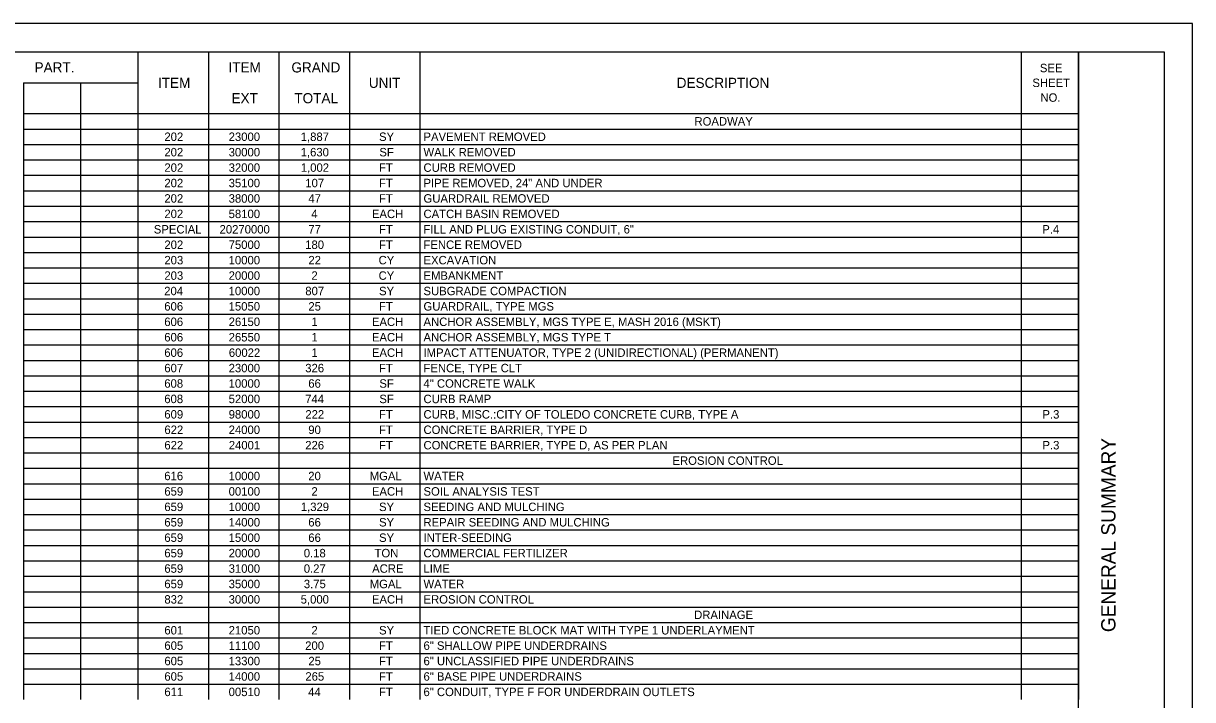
# Model space of a CAD drawing. Extents: x 0 to 34, y 0 to 22.
# Drawn here: x 13.53 to 34, y 10.16 to 22 of the extents above; entities that cross this region are included whole.
import ezdxf

# ---------------------------------------------------------------- set-up
doc = ezdxf.new("R2010")
doc.units = 0
for name, color, linetype in [('Default', 7, 'Continuous'), ('SH_Border', 7, 'Continuous'), ('SH_Cut_Line', 7, 'Continuous'), ('SH_Data', 7, 'Continuous')]:
    doc.layers.add(name, color=color, linetype=linetype)

msp = doc.modelspace()

# ---------------------------------------------------------------- linework, layer by layer
at = {"layer": 'Default'}
for p, q in [((13.53, 21.5), (15.535, 21.5)), ((15.535, 21.5), (32, 21.5)), ((15.535, 21.5), (15.535, 21.23)), ((16.769, 21.5), (16.769, 21.23)), ((18.003, 21.5), (18.003, 21.23)), ((19.237, 21.5), (19.237, 21.23)), ((20.471, 21.5), (20.471, 21.23)), ((30.997, 21.5), (30.997, 21.23)), ((32, 21.5), (32, 21.23)), ((15.535, 21.23), (15.535, 20.96)), ((16.769, 21.23), (16.769, 20.96)), ((18.003, 21.23), (18.003, 20.96)), ((19.237, 21.23), (19.237, 20.96)), ((20.471, 21.23), (20.471, 20.96)), ((30.997, 21.23), (30.997, 20.96)), ((32, 21.23), (32, 20.96)), ((13.53, 20.96), (15.535, 20.96)), ((13.53, 20.96), (13.53, 20.69)), ((14.533, 20.96), (14.533, 20.69)), ((15.535, 20.96), (15.535, 20.69)), ((16.769, 20.96), (16.769, 20.69)), ((18.003, 20.96), (18.003, 20.69)), ((19.237, 20.96), (19.237, 20.69)), ((20.471, 20.96), (20.471, 20.69)), ((30.997, 20.96), (30.997, 20.69)), ((32, 20.96), (32, 20.69)), ((13.53, 20.69), (13.53, 20.42)), ((14.533, 20.69), (14.533, 20.42)), ((15.535, 20.69), (15.535, 20.42)), ((16.769, 20.69), (16.769, 20.42)), ((18.003, 20.69), (18.003, 20.42)), ((19.237, 20.69), (19.237, 20.42)), ((20.471, 20.69), (20.471, 20.42)), ((30.997, 20.69), (30.997, 20.42)), ((32, 20.69), (32, 20.42)), ((13.53, 20.42), (15.535, 20.42)), ((13.53, 20.42), (13.53, 20.15)), ((14.533, 20.42), (14.533, 20.15)), ((15.535, 20.42), (32, 20.42)), ((15.535, 20.42), (15.535, 20.15)), ((16.769, 20.42), (16.769, 20.15)), ((18.003, 20.42), (18.003, 20.15)), ((19.237, 20.42), (19.237, 20.15)), ((20.471, 20.42), (20.471, 20.15)), ((30.997, 20.42), (30.997, 20.15)), ((32, 20.42), (32, 20.15)), ((13.53, 20.15), (15.535, 20.15)), ((13.53, 20.15), (13.53, 18.801)), ((14.533, 20.15), (14.533, 18.801)), ((15.535, 20.15), (32, 20.15)), ((15.535, 20.15), (15.535, 18.801)), ((16.769, 20.15), (16.769, 18.801)), ((18.003, 20.15), (18.003, 18.801)), ((19.237, 20.15), (19.237, 18.801)), ((20.471, 20.15), (20.471, 18.801)), ((30.997, 20.15), (30.997, 18.801)), ((32, 20.15), (32, 18.801)), ((13.53, 19.881), (15.535, 19.881)), ((15.535, 19.881), (32, 19.881)), ((13.53, 19.611), (15.535, 19.611)), ((15.535, 19.611), (32, 19.611)), ((13.53, 19.341), (15.535, 19.341)), ((15.535, 19.341), (32, 19.341)), ((13.53, 19.071), (15.535, 19.071)), ((15.535, 19.071), (32, 19.071)), ((13.53, 18.801), (15.535, 18.801)), ((13.53, 18.801), (13.53, 18.261)), ((14.533, 18.801), (14.533, 18.261)), ((15.535, 18.801), (32, 18.801)), ((15.535, 18.801), (15.535, 18.261)), ((16.769, 18.801), (16.769, 18.261)), ((18.003, 18.801), (18.003, 18.261)), ((19.237, 18.801), (19.237, 18.261)), ((20.471, 18.801), (20.471, 18.261)), ((30.997, 18.801), (30.997, 18.261)), ((32, 18.801), (32, 18.261)), ((13.53, 18.531), (15.535, 18.531)), ((15.535, 18.531), (32, 18.531)), ((13.53, 18.261), (15.535, 18.261)), ((13.53, 18.261), (13.53, 17.991)), ((14.533, 18.261), (14.533, 17.991)), ((15.535, 18.261), (32, 18.261)), ((15.535, 18.261), (15.535, 17.991)), ((16.769, 18.261), (16.769, 17.991)), ((18.003, 18.261), (18.003, 17.991)), ((19.237, 18.261), (19.237, 17.991)), ((20.471, 18.261), (20.471, 17.991)), ((30.997, 18.261), (30.997, 17.991)), ((32, 18.261), (32, 17.991)), ((13.53, 17.991), (15.535, 17.991)), ((13.53, 17.991), (13.53, 17.721)), ((14.533, 17.991), (14.533, 17.721)), ((15.535, 17.991), (32, 17.991)), ((15.535, 17.991), (15.535, 17.721)), ((16.769, 17.991), (16.769, 17.721)), ((18.003, 17.991), (18.003, 17.721)), ((19.237, 17.991), (19.237, 17.721)), ((20.471, 17.991), (20.471, 17.721)), ((30.997, 17.991), (30.997, 17.721)), ((32, 17.991), (32, 17.721)), ((13.53, 17.721), (15.535, 17.721)), ((13.53, 17.721), (13.53, 17.451)), ((14.533, 17.721), (14.533, 17.451)), ((15.535, 17.721), (32, 17.721)), ((15.535, 17.721), (15.535, 17.451)), ((16.769, 17.721), (16.769, 17.451)), ((18.003, 17.721), (18.003, 17.451)), ((19.237, 17.721), (19.237, 17.451)), ((20.471, 17.721), (20.471, 17.451)), ((30.997, 17.721), (30.997, 17.451)), ((32, 17.721), (32, 17.451)), ((13.53, 17.451), (15.535, 17.451)), ((13.53, 17.451), (13.53, 17.181)), ((14.533, 17.451), (14.533, 17.181)), ((15.535, 17.451), (32, 17.451)), ((15.535, 17.451), (15.535, 17.181)), ((16.769, 17.451), (16.769, 17.181)), ((18.003, 17.451), (18.003, 17.181)), ((19.237, 17.451), (19.237, 17.181)), ((20.471, 17.451), (20.471, 17.181)), ((30.997, 17.451), (30.997, 17.181)), ((32, 17.451), (32, 17.181)), ((13.53, 17.181), (15.535, 17.181)), ((13.53, 17.181), (13.53, 16.912)), ((14.533, 17.181), (14.533, 16.912)), ((15.535, 17.181), (32, 17.181)), ((15.535, 17.181), (15.535, 16.912)), ((16.769, 17.181), (16.769, 16.912)), ((18.003, 17.181), (18.003, 16.912)), ((19.237, 17.181), (19.237, 16.912)), ((20.471, 17.181), (20.471, 16.912)), ((30.997, 17.181), (30.997, 16.912)), ((32, 17.181), (32, 16.912)), ((13.53, 16.912), (15.535, 16.912)), ((13.53, 16.912), (13.53, 16.372)), ((14.533, 16.912), (14.533, 16.372)), ((15.535, 16.912), (32, 16.912)), ((15.535, 16.912), (15.535, 16.372)), ((16.769, 16.912), (16.769, 16.372)), ((18.003, 16.912), (18.003, 16.372)), ((19.237, 16.912), (19.237, 16.372)), ((20.471, 16.912), (20.471, 16.372)), ((30.997, 16.912), (30.997, 16.372)), ((32, 16.912), (32, 16.372)), ((13.53, 16.642), (15.535, 16.642)), ((15.535, 16.642), (32, 16.642)), ((13.53, 16.372), (15.535, 16.372)), ((13.53, 16.372), (13.53, 16.102)), ((14.533, 16.372), (14.533, 16.102)), ((15.535, 16.372), (32, 16.372)), ((15.535, 16.372), (15.535, 16.102)), ((16.769, 16.372), (16.769, 16.102)), ((18.003, 16.372), (18.003, 16.102)), ((19.237, 16.372), (19.237, 16.102)), ((20.471, 16.372), (20.471, 16.102)), ((30.997, 16.372), (30.997, 16.102)), ((32, 16.372), (32, 16.102)), ((13.53, 16.102), (15.535, 16.102)), ((13.53, 16.102), (13.53, 15.832)), ((14.533, 16.102), (14.533, 15.832)), ((15.535, 16.102), (32, 16.102)), ((15.535, 16.102), (15.535, 15.832)), ((16.769, 16.102), (16.769, 15.832)), ((18.003, 16.102), (18.003, 15.832)), ((19.237, 16.102), (19.237, 15.832)), ((20.471, 16.102), (20.471, 15.832)), ((30.997, 16.102), (30.997, 15.832)), ((32, 16.102), (32, 15.832)), ((13.53, 15.832), (15.535, 15.832)), ((13.53, 15.832), (13.53, 15.562)), ((14.533, 15.832), (14.533, 15.562)), ((15.535, 15.832), (32, 15.832)), ((15.535, 15.832), (15.535, 15.562)), ((16.769, 15.832), (16.769, 15.562)), ((18.003, 15.832), (18.003, 15.562)), ((19.237, 15.832), (19.237, 15.562)), ((20.471, 15.832), (20.471, 15.562)), ((30.997, 15.832), (30.997, 15.562)), ((32, 15.832), (32, 15.562)), ((13.53, 15.562), (15.535, 15.562)), ((13.53, 15.562), (13.53, 15.022)), ((14.533, 15.562), (14.533, 15.022)), ((15.535, 15.562), (32, 15.562)), ((15.535, 15.562), (15.535, 15.022)), ((16.769, 15.562), (16.769, 15.022)), ((18.003, 15.562), (18.003, 15.022)), ((19.237, 15.562), (19.237, 15.022)), ((20.471, 15.562), (20.471, 15.022)), ((30.997, 15.562), (30.997, 15.022)), ((32, 15.562), (32, 15.022)), ((13.53, 15.292), (15.535, 15.292)), ((15.535, 15.292), (32, 15.292)), ((13.53, 15.022), (15.535, 15.022)), ((13.53, 15.022), (13.53, 14.752)), ((14.533, 15.022), (14.533, 14.752)), ((15.535, 15.022), (32, 15.022)), ((15.535, 15.022), (15.535, 14.752)), ((16.769, 15.022), (16.769, 14.752)), ((18.003, 15.022), (18.003, 14.752)), ((19.237, 15.022), (19.237, 14.752)), ((20.471, 15.022), (20.471, 14.752)), ((30.997, 15.022), (30.997, 14.752)), ((32, 15.022), (32, 14.752)), ((13.53, 14.752), (15.535, 14.752)), ((13.53, 14.752), (13.53, 14.482)), ((14.533, 14.752), (14.533, 14.482)), ((15.535, 14.752), (32, 14.752)), ((15.535, 14.752), (15.535, 14.482)), ((16.769, 14.752), (16.769, 14.482)), ((18.003, 14.752), (18.003, 14.482)), ((19.237, 14.752), (19.237, 14.482)), ((20.471, 14.752), (20.471, 14.482)), ((30.997, 14.752), (30.997, 14.482)), ((32, 14.752), (32, 14.482)), ((13.53, 14.482), (15.535, 14.482)), ((13.53, 14.482), (13.53, 14.212)), ((14.533, 14.482), (14.533, 14.212)), ((15.535, 14.482), (32, 14.482)), ((15.535, 14.482), (15.535, 14.212)), ((16.769, 14.482), (16.769, 14.212)), ((18.003, 14.482), (18.003, 14.212)), ((19.237, 14.482), (19.237, 14.212)), ((20.471, 14.482), (20.471, 14.212)), ((30.997, 14.482), (30.997, 14.212)), ((32, 14.482), (32, 14.212)), ((13.53, 14.212), (15.535, 14.212)), ((13.53, 14.212), (13.53, 12.053)), ((14.533, 14.212), (14.533, 12.053)), ((15.535, 14.212), (32, 14.212)), ((15.535, 14.212), (15.535, 12.053)), ((16.769, 14.212), (16.769, 12.053)), ((18.003, 14.212), (18.003, 12.053)), ((19.237, 14.212), (19.237, 12.053)), ((20.471, 14.212), (20.471, 12.053)), ((30.997, 14.212), (30.997, 12.053)), ((32, 14.212), (32, 12.053)), ((13.53, 13.942), (15.535, 13.942)), ((15.535, 13.942), (32, 13.942)), ((13.53, 13.673), (15.535, 13.673)), ((15.535, 13.673), (32, 13.673)), ((13.53, 13.403), (15.535, 13.403)), ((15.535, 13.403), (32, 13.403)), ((13.53, 13.133), (15.535, 13.133)), ((15.535, 13.133), (32, 13.133)), ((13.53, 12.863), (15.535, 12.863)), ((15.535, 12.863), (32, 12.863)), ((13.53, 12.593), (15.535, 12.593)), ((15.535, 12.593), (32, 12.593)), ((13.53, 12.323), (15.535, 12.323)), ((15.535, 12.323), (32, 12.323)), ((13.53, 12.053), (15.535, 12.053)), ((13.53, 12.053), (13.53, 11.783)), ((14.533, 12.053), (14.533, 11.783)), ((15.535, 12.053), (32, 12.053)), ((15.535, 12.053), (15.535, 11.783)), ((16.769, 12.053), (16.769, 11.783)), ((18.003, 12.053), (18.003, 11.783)), ((19.237, 12.053), (19.237, 11.783)), ((20.471, 12.053), (20.471, 11.783)), ((30.997, 12.053), (30.997, 11.783)), ((32, 12.053), (32, 11.783)), ((13.53, 11.783), (15.535, 11.783)), ((13.53, 11.783), (13.53, 10.704)), ((14.533, 11.783), (14.533, 10.704)), ((15.535, 11.783), (32, 11.783)), ((15.535, 11.783), (15.535, 10.704)), ((16.769, 11.783), (16.769, 10.704)), ((18.003, 11.783), (18.003, 10.704)), ((19.237, 11.783), (19.237, 10.704)), ((20.471, 11.783), (20.471, 10.704)), ((30.997, 11.783), (30.997, 10.704)), ((32, 11.783), (32, 10.704)), ((13.53, 11.513), (15.535, 11.513)), ((15.535, 11.513), (32, 11.513)), ((13.53, 11.243), (15.535, 11.243)), ((15.535, 11.243), (32, 11.243)), ((13.53, 10.973), (15.535, 10.973)), ((15.535, 10.973), (32, 10.973)), ((13.53, 10.704), (15.535, 10.704)), ((13.53, 10.704), (13.53, 10.434)), ((14.533, 10.704), (14.533, 10.434)), ((15.535, 10.704), (32, 10.704)), ((15.535, 10.704), (15.535, 10.434)), ((16.769, 10.704), (16.769, 10.434)), ((18.003, 10.704), (18.003, 10.434)), ((19.237, 10.704), (19.237, 10.434)), ((20.471, 10.704), (20.471, 10.434)), ((30.997, 10.704), (30.997, 10.434)), ((32, 10.704), (32, 10.434)), ((13.53, 10.434), (15.535, 10.434)), ((13.53, 10.434), (13.53, 10.164)), ((14.533, 10.434), (14.533, 10.164)), ((15.535, 10.434), (32, 10.434)), ((15.535, 10.434), (15.535, 10.164)), ((16.769, 10.434), (16.769, 10.164)), ((18.003, 10.434), (18.003, 10.164)), ((19.237, 10.434), (19.237, 10.164)), ((20.471, 10.434), (20.471, 10.164)), ((30.997, 10.434), (30.997, 10.164)), ((32, 10.434), (32, 10.164))]:
    msp.add_line(p, q, dxfattribs=at)
at = {"layer": 'SH_Border'}
msp.add_line((32, 0.5), (32, 21.5), dxfattribs=at)
msp.add_lwpolyline([(1.5, 21.5), (33.5, 21.5), (33.5, 0.5), (1.5, 0.5)], close=True, dxfattribs=at)
at = {"layer": 'SH_Cut_Line'}
msp.add_lwpolyline([(0, 0), (34, 0), (34, 22), (0, 22)], close=True, dxfattribs=at)

# ---------------------------------------------------------------- texts
at = {"layer": 'Default'}
for s, height, p in [('PART.', 0.1774, (13.726, 21.141)), ('ITEM', 0.1774, (17.121, 21.141)), ('GRAND', 0.1774, (18.223, 21.141)), ('SEE ', 0.1478, (31.326, 21.145)), ('ITEM', 0.1774, (15.887, 20.871)), ('UNIT', 0.1774, (19.578, 20.871)), ('DESCRIPTION', 0.17737, (24.968, 20.871)), ('SHEET ', 0.1478, (31.195, 20.886)), ('EXT', 0.1774, (17.174, 20.602)), ('TOTAL', 0.1774, (18.274, 20.602)), ('NO.', 0.1478, (31.336, 20.628)), ('ROADWAY', 0.1478, (25.279, 20.211)), ('202', 0.1478, (15.999, 19.942)), ('23000', 0.1478, (17.124, 19.942)), ('1,887', 0.1478, (18.386, 19.942)), ('SY', 0.1478, (19.757, 19.942)), ('PAVEMENT REMOVED', 0.14781, (20.535, 19.942)), ('202', 0.1478, (15.999, 19.672)), ('30000', 0.1478, (17.124, 19.672)), ('1,630', 0.1478, (18.385, 19.672)), ('SF', 0.1478, (19.762, 19.672)), ('WALK REMOVED', 0.14781, (20.535, 19.672)), ('202', 0.1478, (15.999, 19.402)), ('32000', 0.1478, (17.124, 19.402)), ('1,002', 0.1478, (18.387, 19.402)), ('FT', 0.1478, (19.756, 19.402)), ('CURB REMOVED', 0.14781, (20.535, 19.402)), ('202', 0.1478, (15.999, 19.132)), ('35100', 0.1478, (17.124, 19.132)), ('107', 0.1478, (18.466, 19.132)), ('FT', 0.1478, (19.756, 19.132)), ('PIPE REMOVED, 24" AND UNDER', 0.14781, (20.535, 19.132)), ('202', 0.1478, (15.999, 18.862)), ('38000', 0.1478, (17.124, 18.862)), ('47', 0.1478, (18.519, 18.862)), ('FT', 0.1478, (19.756, 18.862)), ('GUARDRAIL REMOVED', 0.14781, (20.535, 18.862)), ('202', 0.1478, (15.999, 18.592)), ('58100', 0.1478, (17.124, 18.592)), ('4', 0.148, (18.57, 18.592)), ('EACH', 0.1478, (19.632, 18.592)), ('CATCH BASIN REMOVED', 0.14781, (20.535, 18.592)), ('SPECIAL', 0.1478, (15.814, 18.322)), ('20270000', 0.1478, (16.965, 18.322)), ('77', 0.1478, (18.519, 18.322)), ('FT', 0.1478, (19.756, 18.322)), ('FILL AND PLUG EXISTING CONDUIT, 6"', 0.14781, (20.535, 18.322)), ('P.4', 0.1478, (31.368, 18.322)), ('202', 0.1478, (15.999, 18.052)), ('75000', 0.1478, (17.124, 18.052)), ('180', 0.1478, (18.464, 18.052)), ('FT', 0.1478, (19.756, 18.052)), ('FENCE REMOVED', 0.14781, (20.535, 18.052)), ('203', 0.1478, (15.999, 17.782)), ('10000', 0.1478, (17.124, 17.782)), ('22', 0.1478, (18.52, 17.782)), ('CY', 0.1478, (19.749, 17.782)), ('EXCAVATION', 0.1478, (20.535, 17.782)), ('203', 0.1478, (15.999, 17.512)), ('20000', 0.1478, (17.124, 17.512)), ('2', 0.148, (18.573, 17.512)), ('CY', 0.1478, (19.749, 17.512)), ('EMBANKMENT', 0.1478, (20.535, 17.512)), ('204', 0.1478, (15.996, 17.242)), ('10000', 0.1478, (17.124, 17.242)), ('807', 0.1478, (18.466, 17.242)), ('SY', 0.1478, (19.757, 17.242)), ('SUBGRADE COMPACTION', 0.14781, (20.535, 17.242)), ('606', 0.1478, (15.997, 16.973)), ('15050', 0.1478, (17.124, 16.973)), ('25', 0.1478, (18.52, 16.973)), ('FT', 0.1478, (19.756, 16.973)), ('GUARDRAIL, TYPE MGS', 0.14781, (20.535, 16.973)), ('606', 0.1478, (15.997, 16.703)), ('26150', 0.1478, (17.124, 16.703)), ('1', 0.148, (18.573, 16.703)), ('EACH', 0.1478, (19.632, 16.703)), ('ANCHOR ASSEMBLY, MGS TYPE E, MASH 2016 (MSKT)', 0.14781, (20.535, 16.703)), ('606', 0.1478, (15.997, 16.433)), ('26550', 0.1478, (17.124, 16.433)), ('1', 0.148, (18.573, 16.433)), ('EACH', 0.1478, (19.632, 16.433)), ('ANCHOR ASSEMBLY, MGS TYPE T', 0.14781, (20.535, 16.433)), ('606', 0.1478, (15.997, 16.163)), ('60022', 0.1478, (17.127, 16.163)), ('1', 0.148, (18.573, 16.163)), ('EACH', 0.1478, (19.632, 16.163)), ('IMPACT ATTENUATOR, TYPE 2 (UNIDIRECTIONAL) (PERMANENT)', 0.14781, (20.535, 16.163)), ('607', 0.1478, (15.998, 15.893)), ('23000', 0.1478, (17.124, 15.893)), ('326', 0.1478, (18.465, 15.893)), ('FT', 0.1478, (19.756, 15.893)), ('FENCE, TYPE CLT', 0.14781, (20.535, 15.893)), ('608', 0.1478, (15.997, 15.623)), ('10000', 0.1478, (17.124, 15.623)), ('66', 0.1478, (18.518, 15.623)), ('SF', 0.1478, (19.762, 15.623)), ('4" CONCRETE WALK', 0.14781, (20.535, 15.623)), ('608', 0.1478, (15.997, 15.353)), ('52000', 0.1478, (17.124, 15.353)), ('744', 0.1478, (18.464, 15.353)), ('SF', 0.1478, (19.762, 15.353)), ('CURB RAMP', 0.1478, (20.535, 15.353)), ('609', 0.1478, (15.998, 15.083)), ('98000', 0.1478, (17.124, 15.083)), ('222', 0.1478, (18.467, 15.083)), ('FT', 0.1478, (19.756, 15.083)), ('CURB, MISC.:CITY OF TOLEDO CONCRETE CURB, TYPE A', 0.14781, (20.535, 15.083)), ('P.3', 0.1478, (31.371, 15.083)), ('622', 0.1478, (15.999, 14.813)), ('24000', 0.1478, (17.124, 14.813)), ('90', 0.1478, (18.518, 14.813)), ('FT', 0.1478, (19.756, 14.813)), ('CONCRETE BARRIER, TYPE D', 0.14781, (20.535, 14.813)), ('622', 0.1478, (15.999, 14.543)), ('24001', 0.1478, (17.126, 14.543)), ('226', 0.1478, (18.465, 14.543)), ('FT', 0.1478, (19.756, 14.543)), ('CONCRETE BARRIER, TYPE D, AS PER PLAN', 0.14781, (20.535, 14.543)), ('P.3', 0.1478, (31.371, 14.543)), ('EROSION CONTROL', 0.14781, (24.894, 14.273)), ('616', 0.1478, (15.997, 14.004)), ('10000', 0.1478, (17.124, 14.004)), ('20', 0.1478, (18.518, 14.004)), ('MGAL', 0.1478, (19.594, 14.004)), ('WATER', 0.1478, (20.535, 14.004)), ('659', 0.1478, (15.998, 13.734)), ('00100', 0.1478, (17.124, 13.734)), ('2', 0.148, (18.573, 13.734)), ('EACH', 0.1478, (19.632, 13.734)), ('SOIL ANALYSIS TEST', 0.14781, (20.535, 13.734)), ('659', 0.1478, (15.998, 13.464)), ('10000', 0.1478, (17.124, 13.464)), ('1,329', 0.1478, (18.387, 13.464)), ('SY', 0.1478, (19.757, 13.464)), ('SEEDING AND MULCHING', 0.14781, (20.535, 13.464)), ('659', 0.1478, (15.998, 13.194)), ('14000', 0.1478, (17.124, 13.194)), ('66', 0.1478, (18.518, 13.194)), ('SY', 0.1478, (19.757, 13.194)), ('REPAIR SEEDING AND MULCHING', 0.14781, (20.535, 13.194)), ('659', 0.1478, (15.998, 12.924)), ('15000', 0.1478, (17.124, 12.924)), ('66', 0.1478, (18.518, 12.924)), ('SY', 0.1478, (19.757, 12.924)), ('INTER-SEEDING', 0.14781, (20.535, 12.924)), ('659', 0.1478, (15.998, 12.654)), ('20000', 0.1478, (17.124, 12.654)), ('0.18', 0.1478, (18.439, 12.654)), ('TON', 0.1478, (19.678, 12.654)), ('COMMERCIAL FERTILIZER', 0.14781, (20.535, 12.654)), ('659', 0.1478, (15.998, 12.384)), ('31000', 0.1478, (17.124, 12.384)), ('0.27', 0.1478, (18.439, 12.384)), ('ACRE', 0.1478, (19.636, 12.384)), ('LIME', 0.1478, (20.535, 12.384)), ('659', 0.1478, (15.998, 12.114)), ('35000', 0.1478, (17.124, 12.114)), ('3.75', 0.1478, (18.44, 12.114)), ('MGAL', 0.1478, (19.594, 12.114)), ('WATER', 0.1478, (20.535, 12.114)), ('832', 0.1478, (15.999, 11.844)), ('30000', 0.1478, (17.124, 11.844)), ('5,000', 0.1478, (18.385, 11.844)), ('EACH', 0.1478, (19.632, 11.844)), ('EROSION CONTROL', 0.14781, (20.535, 11.844)), ('DRAINAGE', 0.1478, (25.273, 11.574)), ('601', 0.1478, (15.999, 11.304)), ('21050', 0.1478, (17.124, 11.304)), ('2', 0.148, (18.573, 11.304)), ('SY', 0.1478, (19.757, 11.304)), ('TIED CONCRETE BLOCK MAT WITH TYPE 1 UNDERLAYMENT', 0.14781, (20.535, 11.304)), ('605', 0.1478, (15.999, 11.035)), ('11100', 0.1478, (17.124, 11.035)), ('200', 0.1478, (18.464, 11.035)), ('FT', 0.1478, (19.756, 11.035)), ('6" SHALLOW PIPE UNDERDRAINS', 0.14781, (20.535, 11.035)), ('605', 0.1478, (15.999, 10.765)), ('13300', 0.1478, (17.124, 10.765)), ('25', 0.1478, (18.52, 10.765)), ('FT', 0.1478, (19.756, 10.765)), ('6" UNCLASSIFIED PIPE UNDERDRAINS', 0.14781, (20.535, 10.765)), ('605', 0.1478, (15.999, 10.495)), ('14000', 0.1478, (17.124, 10.495)), ('265', 0.1478, (18.467, 10.495)), ('6" BASE PIPE UNDERDRAINS', 0.14781, (20.535, 10.495)), ('FT', 0.1478, (19.756, 10.495)), ('611', 0.1478, (15.999, 10.225)), ('00510', 0.1478, (17.124, 10.225)), ('44', 0.1478, (18.517, 10.225)), ('FT', 0.1478, (19.756, 10.225)), ('6" CONDUIT, TYPE F FOR UNDERDRAIN OUTLETS', 0.14781, (20.535, 10.225))]:
    msp.add_text(s, height=height, dxfattribs=at).set_placement(p)
at = {"layer": 'SH_Data'}
msp.add_text('GENERAL SUMMARY', height=0.25, rotation=90, dxfattribs=at).set_placement((32.65, 11.344))

doc.saveas('drawing.dxf')
